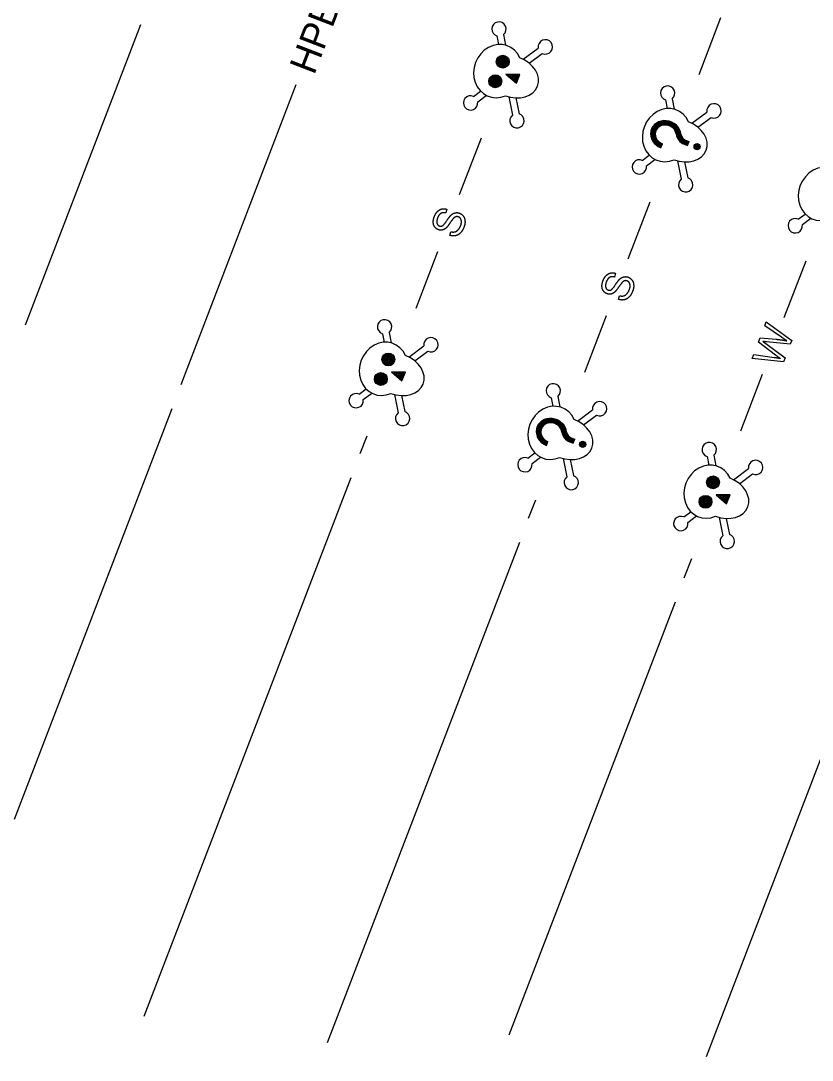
# Model space of a CAD drawing. Extents: x 1015221 to 1064345, y 619216 to 647967.
# Drawn here: x 1047582 to 1048271, y 626200 to 627103 of the extents above; entities that cross this region are included whole.
import ezdxf

# ---------------------------------------------------------------- set-up
doc = ezdxf.new("R2010")
doc.units = 0
doc.layers.add('Default', color=7, linetype='Continuous')

msp = doc.modelspace()

# ---------------------------------------------------------------- linework, layer by layer
at = {"layer": 'Default'}
for p, q in [((1048172.18, 627056.76), (1048191.13, 627106.08)), ((1047586.31, 626838.96), (1047686.59, 627099.98)), ((1047996.28, 627090.15), (1047997.74, 627082.73)), ((1048002.05, 627091.28), (1048003.86, 627082.12)), ((1048019.22, 627069.89), (1048032.28, 627079.67)), ((1048024.45, 627066.45), (1048035.81, 627074.96)), ((1048005.94, 627056.27), (1048005.94, 627056.27)), ((1047721.61, 626786.98), (1047821.89, 627048)), ((1047976.08, 627037.57), (1047982.13, 627042.11)), ((1047979.6, 627032.86), (1047987.08, 627038.46)), ((1048006.68, 627037.25), (1048009.83, 627021.25)), ((1048012.87, 627036.3), (1048015.61, 627022.38)), ((1048142.99, 627034.48), (1048144.45, 627027.05)), ((1048148.77, 627035.61), (1048150.57, 627026.44)), ((1048165.94, 627014.22), (1048179, 627024)), ((1048171.17, 627010.78), (1048182.53, 627019.29)), ((1047963.89, 626952.16), (1047982.83, 627001.47)), ((1048138.86, 626992.9), (1048140.2, 626996.4)), ((1048150.87, 627001.28), (1048150.87, 627001.28)), ((1048159.04, 626996.13), (1048162.11, 626994.96)), ((1048159.23, 626996.63), (1048162.3, 626995.45)), ((1048159.42, 626997.13), (1048162.49, 626995.95)), ((1048159.62, 626997.63), (1048162.69, 626996.45)), ((1048159.81, 626998.13), (1048162.88, 626996.95)), ((1048160, 626998.63), (1048163.07, 626997.45)), ((1048160.19, 626999.13), (1048163.26, 626997.95)), ((1048160.38, 626999.63), (1048163.45, 626998.45)), ((1048162.11, 626994.96), (1048163.45, 626998.45)), ((1048122.79, 626981.9), (1048128.85, 626986.43)), ((1048126.32, 626977.19), (1048133.8, 626982.79)), ((1048153.4, 626981.58), (1048156.55, 626965.57)), ((1048159.59, 626980.63), (1048162.33, 626966.71)), ((1048110.6, 626896.48), (1048129.55, 626945.8)), ((1047952.81, 626939.43), (1047951.85, 626936.22)), ((1048258.43, 626930.78), (1048264.48, 626935.32)), ((1048261.96, 626926.07), (1048269.44, 626931.67)), ((1047955.33, 626916.76), (1047956.25, 626919.94)), ((1047925.99, 626853.52), (1047944.94, 626902.84)), ((1048246.24, 626845.37), (1048265.18, 626894.68)), ((1048099.52, 626883.76), (1048098.57, 626880.54)), ((1048102.05, 626861.09), (1048102.97, 626864.27)), ((1048072.71, 626797.85), (1048091.66, 626847.17)), ((1047902.58, 626832.37), (1047904.38, 626823.21)), ((1047896.8, 626831.24), (1047898.26, 626823.81)), ((1047919.75, 626810.98), (1047932.81, 626820.76)), ((1047924.98, 626807.54), (1047936.33, 626816.05)), ((1047906.47, 626797.35), (1047906.47, 626797.35)), ((1048208.34, 626746.73), (1048227.29, 626796.05)), ((1047876.6, 626778.66), (1047882.66, 626783.2)), ((1047880.13, 626773.95), (1047887.61, 626779.55)), ((1047907.21, 626778.34), (1047910.36, 626762.34)), ((1047913.4, 626777.39), (1047916.13, 626763.47)), ((1048043.52, 626775.56), (1048044.98, 626768.14)), ((1048049.29, 626776.7), (1048051.1, 626767.53)), ((1047713.52, 626765.92), (1047576.37, 626408.96)), ((1048066.46, 626755.31), (1048079.52, 626765.09)), ((1048071.7, 626751.87), (1048083.05, 626760.38)), ((1047877.42, 626727.12), (1047883.36, 626742.56)), ((1048051.39, 626742.37), (1048051.39, 626742.37)), ((1048039.38, 626733.99), (1048040.73, 626737.49)), ((1048059.57, 626737.22), (1048062.64, 626736.04)), ((1048059.76, 626737.72), (1048062.83, 626736.54)), ((1048059.95, 626738.22), (1048063.02, 626737.04)), ((1048060.14, 626738.72), (1048063.21, 626737.54)), ((1048060.33, 626739.22), (1048063.4, 626738.04)), ((1048060.53, 626739.72), (1048063.59, 626738.54)), ((1048060.72, 626740.22), (1048063.79, 626739.04)), ((1048060.91, 626740.72), (1048063.98, 626739.54)), ((1048062.64, 626736.04), (1048063.98, 626739.54)), ((1048023.32, 626722.99), (1048029.37, 626727.52)), ((1048026.85, 626718.28), (1048034.33, 626723.88)), ((1048179.15, 626724.45), (1048180.61, 626717.02)), ((1048184.93, 626725.58), (1048186.73, 626716.41)), ((1048053.93, 626722.67), (1048057.08, 626706.66)), ((1048060.11, 626721.72), (1048062.85, 626707.8)), ((1047869.43, 626706.02), (1047689.4, 626237.47)), ((1048202.1, 626704.19), (1048215.16, 626713.97)), ((1048207.33, 626700.75), (1048218.69, 626709.26)), ((1048188.82, 626690.56), (1048188.82, 626690.56)), ((1048023.91, 626670.84), (1048030.08, 626686.89)), ((1048158.95, 626671.87), (1048165.01, 626676.41)), ((1048162.48, 626667.16), (1048169.96, 626672.76)), ((1048189.56, 626671.55), (1048192.71, 626655.54)), ((1048195.75, 626670.6), (1048198.49, 626656.68)), ((1048015.91, 626649.74), (1047848.69, 626214.5)), ((1048159.21, 626618.85), (1048165.71, 626635.77)), ((1048151.21, 626597.76), (1048006.57, 626221.3)), ((1048307.03, 626537.9), (1048178.2, 626202.58))]:
    msp.add_line(p, q, dxfattribs=at)
for points in [[(1048004.15, 627056.95), (1048013.22, 627049.04), (1048016.19, 627056.76)], [(1048005.94, 627056.27), (1048012.94, 627050.16), (1048015.23, 627056.12)], [(1048007.74, 627055.58), (1048012.66, 627051.27), (1048014.28, 627055.47)], [(1048009.53, 627054.89), (1048012.39, 627052.39), (1048013.32, 627054.83)], [(1048011.32, 627054.2), (1048012.11, 627053.51), (1048012.36, 627054.18)], [(1047904.67, 626798.04), (1047913.74, 626790.13), (1047916.71, 626797.85)], [(1047906.47, 626797.35), (1047913.47, 626791.25), (1047915.76, 626797.21)], [(1047908.26, 626796.67), (1047913.19, 626792.36), (1047914.8, 626796.56)], [(1047910.05, 626795.98), (1047912.91, 626793.48), (1047913.85, 626795.92)], [(1047911.85, 626795.29), (1047912.63, 626794.6), (1047912.89, 626795.27)], [(1048187.03, 626691.25), (1048196.09, 626683.34), (1048199.06, 626691.06)], [(1048188.82, 626690.56), (1048195.82, 626684.45), (1048198.11, 626690.42)], [(1048190.61, 626689.88), (1048195.54, 626685.57), (1048197.15, 626689.77)], [(1048192.41, 626689.19), (1048195.26, 626686.69), (1048196.2, 626689.13)], [(1048194.2, 626688.5), (1048194.98, 626687.81), (1048195.24, 626688.48)]]:
    msp.add_lwpolyline(points, close=True, dxfattribs=at)
for points in [[(1048243.7, 626828.28), (1048229.34, 626838.22), (1048230.6, 626841.51), (1048252.68, 626825.3), (1048251.45, 626822.12), (1048230.68, 626824.17)], [(1048238.63, 626812.66), (1048223.78, 626823.75), (1048225.29, 626827.69), (1048239.13, 626826.43)], [(1048230.09, 626822.65), (1048246.89, 626810.23), (1048245.59, 626806.87), (1048218.42, 626809.8), (1048219.71, 626813.15), (1048237.32, 626810.69)]]:
    msp.add_lwpolyline(points, dxfattribs=at)
for centre, radius in [((1048001.41, 627067.76), 5.6), ((1048001.41, 627067.76), 4.94), ((1048001.41, 627067.76), 4.28), ((1048001.41, 627067.76), 3.62), ((1048001.41, 627067.76), 2.96), ((1048001.41, 627067.76), 2.3), ((1048001.41, 627067.76), 1.64), ((1048001.41, 627067.76), 0.977), ((1048001.41, 627067.76), 0.317), ((1047994.88, 627050.76), 5.6), ((1047994.88, 627050.76), 4.94), ((1047994.88, 627050.76), 4.28), ((1047994.88, 627050.76), 3.62), ((1047994.88, 627050.76), 2.96), ((1047994.88, 627050.76), 2.3), ((1047994.88, 627050.76), 1.64), ((1047994.88, 627050.76), 0.977), ((1047994.88, 627050.76), 0.317), ((1048170.42, 626993.91), 2.67), ((1048170.42, 626993.91), 2.08), ((1048170.42, 626993.91), 1.47), ((1048170.42, 626993.91), 0.879), ((1048170.42, 626993.91), 0.285), ((1047901.94, 626808.84), 5.6), ((1047901.94, 626808.84), 4.94), ((1047901.94, 626808.84), 4.28), ((1047901.94, 626808.84), 3.62), ((1047901.94, 626808.84), 2.96), ((1047901.94, 626808.84), 2.3), ((1047901.94, 626808.84), 1.64), ((1047901.94, 626808.84), 0.977), ((1047901.94, 626808.84), 0.317), ((1047895.41, 626791.85), 5.6), ((1047895.41, 626791.85), 4.94), ((1047895.41, 626791.85), 4.28), ((1047895.41, 626791.85), 3.62), ((1047895.41, 626791.85), 2.96), ((1047895.41, 626791.85), 2.3), ((1047895.41, 626791.85), 1.64), ((1047895.41, 626791.85), 0.977), ((1047895.41, 626791.85), 0.317), ((1048070.95, 626735), 2.67), ((1048070.95, 626735), 2.08), ((1048070.95, 626735), 1.47), ((1048070.95, 626735), 0.879), ((1048070.95, 626735), 0.285), ((1048184.29, 626702.05), 5.6), ((1048184.29, 626702.05), 4.94), ((1048184.29, 626702.05), 4.28), ((1048184.29, 626702.05), 3.62), ((1048184.29, 626702.05), 2.96), ((1048184.29, 626702.05), 2.3), ((1048184.29, 626702.05), 1.64), ((1048184.29, 626702.05), 0.977), ((1048184.29, 626702.05), 0.317), ((1048177.76, 626685.06), 5.6), ((1048177.76, 626685.06), 4.94), ((1048177.76, 626685.06), 4.28), ((1048177.76, 626685.06), 3.62), ((1048177.76, 626685.06), 2.96), ((1048177.76, 626685.06), 2.3), ((1048177.76, 626685.06), 1.64), ((1048177.76, 626685.06), 0.977), ((1048177.76, 626685.06), 0.317)]:
    msp.add_circle(centre, radius, dxfattribs=at)
for centre, start, end in [((1047998.1, 627096.14), 309.17685, 253.08541), ((1048038.47, 627080.63), 244.88064, 188.78919), ((1048144.81, 627040.46), 309.17685, 253.08541), ((1047973.42, 627031.9), 64.88064, 8.78919), ((1048185.18, 627024.95), 244.88064, 188.78919), ((1048013.79, 627016.39), 129.17685, 73.08541), ((1048120.13, 626976.23), 64.88064, 8.78919), ((1048160.5, 626960.72), 129.17685, 73.08541), ((1048255.77, 626925.11), 64.88064, 8.78919), ((1047898.62, 626837.23), 309.17685, 253.08541), ((1047938.99, 626821.72), 244.88064, 188.78919), ((1048045.34, 626781.55), 309.17685, 253.08541), ((1047873.94, 626772.99), 64.88064, 8.78919), ((1048085.71, 626766.04), 244.88064, 188.78919), ((1047914.31, 626757.48), 129.17685, 73.08541), ((1048180.97, 626730.44), 309.17685, 253.08541), ((1048020.66, 626717.32), 64.88064, 8.78919), ((1048221.34, 626714.93), 244.88064, 188.78919), ((1048061.03, 626701.81), 129.17685, 73.08541), ((1048156.29, 626666.2), 64.88064, 8.78919), ((1048196.66, 626650.69), 129.17685, 73.08541)]:
    msp.add_arc(centre, 6.26, start, end, dxfattribs=at)
for centre, major_axis, ratio, start_param, end_param in [((1047997.22, 627059.61), (8.42, 21.92), 0.885014, 5.564242, 10.143721), ((1048009.77, 627054.79), (21.92, -8.42), 0.752542, 4.722735, 7.843636), ((1048143.94, 627003.94), (8.42, 21.92), 0.885014, 5.564242, 10.143721), ((1048143.21, 627004.22), (-12.58, 4.83), 0.9, 3.567618, 7.853982), ((1048143.21, 627004.22), (-12.02, 4.62), 0.9, 3.567618, 7.853982), ((1048143.21, 627004.22), (-11.47, 4.41), 0.9, 3.567618, 7.853982), ((1048143.21, 627004.22), (-10.91, 4.19), 0.9, 3.567618, 7.853982), ((1048143.21, 627004.22), (-10.36, 3.98), 0.9, 3.567618, 7.853982), ((1048143.21, 627004.22), (-9.8, 3.77), 0.9, 3.567618, 7.853982), ((1048143.21, 627004.22), (-9.25, 3.55), 0.9, 3.567618, 7.853982), ((1048143.21, 627004.22), (-8.69, 3.34), 0.9, 3.567618, 7.853982), ((1048156.49, 626999.12), (21.92, -8.42), 0.752542, 4.722735, 7.843636), ((1048162.3, 627004.62), (-9.43, 3.62), 0.9, 0.426026, 1.570796), ((1048162.3, 627004.62), (-8.88, 3.41), 0.9, 0.426026, 1.570796), ((1048162.3, 627004.62), (-8.32, 3.2), 0.9, 0.426026, 1.570796), ((1048162.3, 627004.62), (-7.77, 2.98), 0.9, 0.426026, 1.570796), ((1048162.3, 627004.62), (-7.21, 2.77), 0.9, 0.426026, 1.570796), ((1048162.3, 627004.62), (-6.66, 2.56), 0.9, 0.426026, 1.570796), ((1048162.3, 627004.62), (-6.1, 2.34), 0.9, 0.426026, 1.570796), ((1048162.3, 627004.62), (-5.55, 2.13), 0.9, 0.426026, 1.570796), ((1048279.58, 626952.82), (8.42, 21.92), 0.885014, 5.564242, 10.143721), ((1047897.75, 626800.7), (8.42, 21.92), 0.885014, 5.564242, 10.143721), ((1047910.3, 626795.88), (21.92, -8.42), 0.752542, 4.722735, 7.843636), ((1048044.47, 626745.03), (8.42, 21.92), 0.885014, 5.564242, 10.143721), ((1048043.73, 626745.31), (-12.58, 4.83), 0.9, 3.567618, 7.853982), ((1048043.73, 626745.31), (-12.02, 4.62), 0.9, 3.567618, 7.853982), ((1048043.73, 626745.31), (-11.47, 4.41), 0.9, 3.567618, 7.853982), ((1048043.73, 626745.31), (-10.91, 4.19), 0.9, 3.567618, 7.853982), ((1048043.73, 626745.31), (-10.36, 3.98), 0.9, 3.567618, 7.853982), ((1048043.73, 626745.31), (-9.8, 3.77), 0.9, 3.567618, 7.853982), ((1048043.73, 626745.31), (-9.25, 3.55), 0.9, 3.567618, 7.853982), ((1048043.73, 626745.31), (-8.69, 3.34), 0.9, 3.567618, 7.853982), ((1048057.01, 626740.21), (21.92, -8.42), 0.752542, 4.722735, 7.843636), ((1048062.83, 626745.71), (-9.43, 3.62), 0.9, 0.426026, 1.570796), ((1048062.83, 626745.71), (-8.88, 3.41), 0.9, 0.426026, 1.570796), ((1048062.83, 626745.71), (-8.32, 3.2), 0.9, 0.426026, 1.570796), ((1048062.83, 626745.71), (-7.77, 2.98), 0.9, 0.426026, 1.570796), ((1048062.83, 626745.71), (-7.21, 2.77), 0.9, 0.426026, 1.570796), ((1048062.83, 626745.71), (-6.66, 2.56), 0.9, 0.426026, 1.570796), ((1048062.83, 626745.71), (-6.1, 2.34), 0.9, 0.426026, 1.570796), ((1048062.83, 626745.71), (-5.55, 2.13), 0.9, 0.426026, 1.570796), ((1048180.1, 626693.91), (8.42, 21.92), 0.885014, 5.564242, 10.143721), ((1048192.65, 626689.09), (21.92, -8.42), 0.752542, 4.722735, 7.843636)]:
    msp.add_ellipse(centre, major_axis=major_axis, ratio=ratio, start_param=start_param, end_param=end_param, dxfattribs=at)
for points in [[(1047940.97, 626928.11), (1047940.91, 626930.48), (1047941.87, 626932.97)], [(1047941.87, 626932.97), (1047942.93, 626935.72), (1047944.61, 626937.48)], [(1047944.8, 626932), (1047943.65, 626929.03), (1047944.22, 626927.25)], [(1047944.61, 626937.48), (1047946.3, 626939.24), (1047948.45, 626939.71)], [(1047947.65, 626935.86), (1047945.89, 626934.86), (1047944.8, 626932)], [(1047951.85, 626936.22), (1047949.41, 626936.86), (1047947.65, 626935.86)], [(1047948.45, 626939.71), (1047950.6, 626940.18), (1047952.81, 626939.43)], [(1047952.53, 626929.27), (1047954.97, 626932.92), (1047956.21, 626934.14)], [(1047958.32, 626931.23), (1047957.54, 626930.38), (1047955.42, 626927.28)], [(1047956.21, 626934.14), (1047958.03, 626935.91), (1047959.94, 626936.35)], [(1047960.63, 626932.9), (1047959.5, 626932.56), (1047958.32, 626931.23)], [(1047959.94, 626936.35), (1047961.86, 626936.79), (1047963.84, 626936.03)], [(1047962.91, 626932.79), (1047961.75, 626933.23), (1047960.63, 626932.9)], [(1047964.76, 626931.28), (1047964.06, 626932.35), (1047962.91, 626932.79)], [(1047963.84, 626936.03), (1047965.81, 626935.27), (1047967.12, 626933.48)], [(1047965.46, 626928.56), (1047965.46, 626930.2), (1047964.76, 626931.28)], [(1047967.12, 626933.48), (1047968.42, 626931.68), (1047968.58, 626929.2)], [(1047942.24, 626924.06), (1047941.03, 626925.75), (1047940.97, 626928.11)], [(1047945.33, 626921.66), (1047943.46, 626922.38), (1047942.24, 626924.06)], [(1047944.22, 626927.25), (1047944.78, 626925.47), (1047946.31, 626924.88)], [(1047946.31, 626924.88), (1047947.64, 626924.37), (1047948.87, 626925.01)], [(1047952.04, 626923.1), (1047950.44, 626921.69), (1047948.73, 626921.35)], [(1047948.87, 626925.01), (1047950.09, 626925.62), (1047952.53, 626929.27)], [(1047955.42, 626927.28), (1047953.29, 626924.18), (1047952.04, 626923.1)], [(1047962.56, 626921.54), (1047963.94, 626922.94), (1047964.75, 626925.05)], [(1047967.72, 626924.07), (1047966.43, 626920.72), (1047964.59, 626918.83)], [(1047964.75, 626925.05), (1047965.47, 626926.91), (1047965.46, 626928.56)], [(1047968.58, 626929.2), (1047968.73, 626926.71), (1047967.72, 626924.07)], [(1047948.73, 626921.35), (1047947.03, 626921.01), (1047945.33, 626921.66)], [(1047960.29, 626916.41), (1047957.83, 626915.88), (1047955.33, 626916.76)], [(1047956.25, 626919.94), (1047958.19, 626919.45), (1047959.69, 626919.79)], [(1047959.69, 626919.79), (1047961.18, 626920.14), (1047962.56, 626921.54)], [(1047964.59, 626918.83), (1047962.74, 626916.95), (1047960.29, 626916.41)], [(1048087.69, 626872.44), (1048087.63, 626874.8), (1048088.59, 626877.3)], [(1048088.59, 626877.3), (1048089.64, 626880.05), (1048091.33, 626881.81)], [(1048091.33, 626881.81), (1048093.02, 626883.56), (1048095.17, 626884.03)], [(1048094.37, 626880.19), (1048092.61, 626879.18), (1048091.51, 626876.33)], [(1048098.57, 626880.54), (1048096.13, 626881.19), (1048094.37, 626880.19)], [(1048095.17, 626884.03), (1048097.32, 626884.51), (1048099.52, 626883.76)], [(1048099.25, 626873.6), (1048101.68, 626877.25), (1048102.92, 626878.47)], [(1048102.92, 626878.47), (1048104.74, 626880.24), (1048106.66, 626880.68)], [(1048107.34, 626877.22), (1048106.22, 626876.88), (1048105.03, 626875.56)], [(1048106.66, 626880.68), (1048108.57, 626881.12), (1048110.56, 626880.36)], [(1048109.63, 626877.11), (1048108.47, 626877.56), (1048107.34, 626877.22)], [(1048111.47, 626875.6), (1048110.77, 626876.67), (1048109.63, 626877.11)], [(1048110.56, 626880.36), (1048112.53, 626879.6), (1048113.83, 626877.8)], [(1048113.83, 626877.8), (1048115.14, 626876.01), (1048115.3, 626873.52)], [(1048088.96, 626868.39), (1048087.74, 626870.08), (1048087.69, 626872.44)], [(1048092.04, 626865.99), (1048090.18, 626866.71), (1048088.96, 626868.39)], [(1048091.51, 626876.33), (1048090.37, 626873.35), (1048090.93, 626871.58)], [(1048090.93, 626871.58), (1048091.5, 626869.8), (1048093.03, 626869.21)], [(1048093.03, 626869.21), (1048094.36, 626868.7), (1048095.59, 626869.33)], [(1048095.59, 626869.33), (1048096.81, 626869.95), (1048099.25, 626873.6)], [(1048102.13, 626871.61), (1048100.01, 626868.51), (1048098.76, 626867.42)], [(1048105.03, 626875.56), (1048104.26, 626874.71), (1048102.13, 626871.61)], [(1048109.28, 626865.87), (1048110.66, 626867.27), (1048111.47, 626869.37)], [(1048114.44, 626868.4), (1048113.15, 626865.05), (1048111.3, 626863.16)], [(1048112.18, 626872.89), (1048112.17, 626874.53), (1048111.47, 626875.6)], [(1048111.47, 626869.37), (1048112.18, 626871.24), (1048112.18, 626872.89)], [(1048115.3, 626873.52), (1048115.45, 626871.04), (1048114.44, 626868.4)], [(1048095.45, 626865.67), (1048093.74, 626865.33), (1048092.04, 626865.99)], [(1048098.76, 626867.42), (1048097.15, 626866.01), (1048095.45, 626865.67)], [(1048107, 626860.74), (1048104.55, 626860.2), (1048102.05, 626861.09)], [(1048102.97, 626864.27), (1048104.91, 626863.78), (1048106.4, 626864.12)], [(1048106.4, 626864.12), (1048107.9, 626864.46), (1048109.28, 626865.87)], [(1048111.3, 626863.16), (1048109.46, 626861.27), (1048107, 626860.74)], [(1048230.68, 626824.17), (1048228.07, 626824.41), (1048227.48, 626824.49)], [(1048227.48, 626824.49), (1048229.02, 626823.43), (1048230.09, 626822.65)], [(1048239.13, 626826.43), (1048244.28, 626825.95), (1048248.6, 626824.98)], [(1048248.6, 626824.98), (1048246.45, 626826.36), (1048243.7, 626828.28)], [(1048237.32, 626810.69), (1048240.09, 626810.33), (1048242.76, 626809.8)], [(1048242.76, 626809.8), (1048239.17, 626812.26), (1048238.63, 626812.66)]]:
    msp.add_open_spline(points, degree=2, dxfattribs=at)

# ---------------------------------------------------------------- texts
for s, height, p in [('HPB', 23.539, (1047837.38, 627055.49)), ('BUILDINGS AND OTHER CULTURE:', 86.3081, (1047928.73, 624549.23))]:
    msp.add_text(s, height=height, rotation=68.98302, dxfattribs=at).set_placement(p)

doc.saveas('drawing.dxf')
